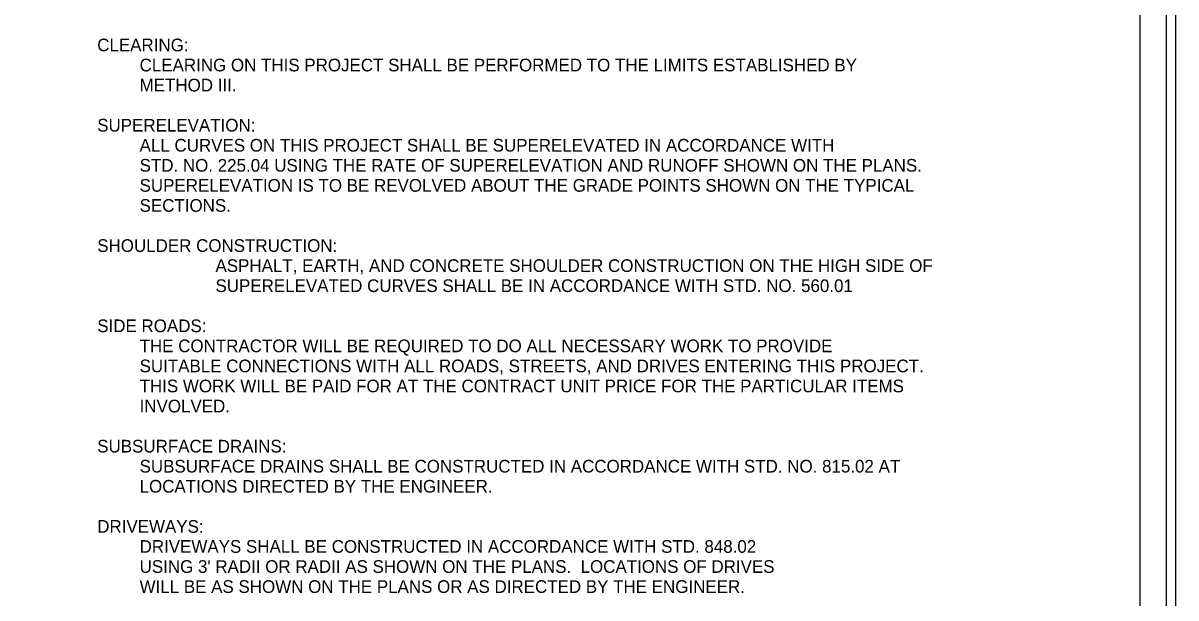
# Model space of a CAD drawing. Extents: x 775818 to 777502, y 889228 to 890323.
# Drawn here: x 776956 to 777502, y 889769 to 890041 of the extents above; entities that cross this region are included whole.
import ezdxf

# ---------------------------------------------------------------- set-up
doc = ezdxf.new("R2010")
doc.units = 0
for name, color, linetype in [('Sheet Data Text CELL', 7, 'Continuous'), ('Sheet Plan CELL', 7, 'Continuous'), ('Sheet Plot Border Inside CELL', 7, 'Continuous'), ('Sheet Plot Border Outside CELL', 7, 'Continuous')]:
    doc.layers.add(name, color=color, linetype=linetype)

msp = doc.modelspace()

# ---------------------------------------------------------------- linework, layer by layer
at = {"layer": 'Sheet Plan CELL'}
msp.add_lwpolyline([(777484.78, 890300.81), (775984.78, 890300.81), (775984.78, 889250.81), (777484.78, 889250.81)], close=True, dxfattribs=at)
at = {"layer": 'Sheet Plot Border Inside CELL'}
msp.add_lwpolyline([(775831.28, 889248.31), (777497.28, 889248.31), (777497.28, 890303.31), (775831.28, 890303.31)], close=True, dxfattribs=at)
at = {"layer": 'Sheet Plot Border Outside CELL'}
msp.add_lwpolyline([(775818.28, 889228.31), (777501.78, 889228.31), (777501.78, 890323.31), (775818.28, 890323.31)], close=True, dxfattribs=at)

# ---------------------------------------------------------------- texts
at = {"layer": 'Sheet Data Text CELL'}
for s, p in [('CLEARING:  ', (776990.94, 890028.07)), ('         CLEARING ON THIS PROJECT SHALL BE PERFORMED TO THE LIMITS ESTABLISHED BY ', (776990.94, 890018.57)), ('         METHOD III.', (776990.94, 890009.07)), ('SUPERELEVATION:  ', (776990.94, 889990.07)), ('         ALL CURVES ON THIS PROJECT SHALL BE SUPERELEVATED IN ACCORDANCE WITH', (776990.94, 889980.57)), ('         STD. NO. 225.04 USING THE RATE OF SUPERELEVATION AND RUNOFF SHOWN ON THE PLANS.', (776990.94, 889971.07)), ('         SUPERELEVATION IS TO BE REVOLVED ABOUT THE GRADE POINTS SHOWN ON THE TYPICAL ', (776990.94, 889961.57)), ('         SECTIONS.  ', (776990.94, 889952.07)), ('SHOULDER CONSTRUCTION:', (776990.94, 889933.07)), ('ASPHALT, EARTH, AND CONCRETE SHOULDER CONSTRUCTION ON THE HIGH SIDE OF', (777046.94, 889923.57)), ('SUPERELEVATED CURVES SHALL BE IN ACCORDANCE WITH STD. NO. 560.01', (777046.94, 889914.07)), ('SIDE ROADS:  ', (776990.94, 889895.07)), ('         THE CONTRACTOR WILL BE REQUIRED TO DO ALL NECESSARY WORK TO PROVIDE ', (776990.94, 889885.57)), ('         SUITABLE CONNECTIONS WITH ALL ROADS, STREETS, AND DRIVES ENTERING THIS PROJECT.  ', (776990.94, 889876.07)), ('         THIS WORK WILL BE PAID FOR AT THE CONTRACT UNIT PRICE FOR THE PARTICULAR ITEMS ', (776990.94, 889866.57)), ('         INVOLVED.  ', (776990.94, 889857.07)), ('SUBSURFACE DRAINS:', (776990.94, 889838.07)), ('         SUBSURFACE DRAINS SHALL BE CONSTRUCTED IN ACCORDANCE WITH STD. NO. 815.02 AT ', (776990.94, 889828.57)), ('         LOCATIONS DIRECTED BY THE ENGINEER.  ', (776990.94, 889819.07)), ('DRIVEWAYS:  ', (776990.94, 889800.07)), ('         DRIVEWAYS SHALL BE CONSTRUCTED IN ACCORDANCE WITH STD. 848.02', (776990.94, 889790.57)), ("         USING 3' RADII OR RADII AS SHOWN ON THE PLANS.  LOCATIONS OF DRIVES", (776990.94, 889781.07)), ('         WILL BE AS SHOWN ON THE PLANS OR AS DIRECTED BY THE ENGINEER.  ', (776990.94, 889771.57))]:
    msp.add_text(s, height=6, dxfattribs=at).set_placement(p)

doc.saveas('drawing.dxf')
